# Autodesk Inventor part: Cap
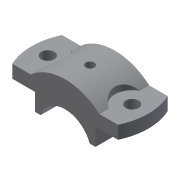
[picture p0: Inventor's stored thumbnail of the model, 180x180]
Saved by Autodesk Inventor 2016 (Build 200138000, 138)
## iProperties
Created: 2009-04
Part Number: Cap
Document SubType Name: Modeling
Designer: Sham
Density: 1 g/cm^3
Material: Generic
Appearance: Default
Author: Sham
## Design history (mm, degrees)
sketch "Sketch1"
  geometry: L1 (-48.857, 23)-(48.857, 23); L2 (48.857, -23)-(-48.857, -23); A1 r 54 centre (0, 0) between (-48.857, 23) and (-48.857, -23); A2 r 54 centre (0, 0) between (48.857, -23) and (48.857, 23); 1 further point
  constraints: 4 end point, 4 point on circle, 2 centre point, 2 coincident, 1 horizontal, 1 parallel, 1 other
  dimensions: "d3" = 54 radius of A1; "d4" = 54 radius of A2; "d5" = 46 distance between parallel lines of L2 L1; "d6" = 23 distance from line of point (0, 0) L1
extrude "Extrusion1" new body sketch "Sketch1" distance "d7" = 12; taper "d8" = 0 deg
sketch "Sketch3"
  geometry: L1 (20.906, 0)-(20.906, -16); L2 (76.906, -0.137)-(76.906, -16.137); L3 (20.906, -16)-(26.23, -16); L4 (71.532, -16.137)-(76.906, -16.137); L5 (76.906, -0.137)-(76.857, 12); L6 (97.714, 0)-(0, 0) reference; L7 (76.857, 12)-(80.606, 12); L8 (17.108, 12)-(20.906, 12); L9 (20.906, 12)-(20.906, 0); L10 (0, 12)-(97.714, 12) reference; A1 r 24 centre (48.857, -24) between (71.532, -16.137) and (26.23, -16); A2 r 48 centre (48.857, -24) between (80.606, 12) and (17.108, 12); 3 further points
  constraints: 16 end point, 4 point on circle, 3 parallel, 3 perpendicular, 2 centre point, 2 coincident, 2 vertical alignment, 1 collinear, 1 midpoint, 1 vertical, 2 other
  dimensions: "d17" = 48 diameter of A1; "d18" = 16 distance of L1.start L1.end; "d19" = 56 distance between parallel lines of L2 L1; "d21" = 8 vertical distance of A1.centre L1.end; "d22" = 48 radius of A2; "d23" = 0 distance from line of L6 L1.start; "d38" = 31.74902 distance of L7.end point (48.857, 12); "d39" = 28 distance from line of point (48.857, 12) L5
extrude "Extrusion2" join sketch "Sketch3" stored distance "d24" = 12; taper "d25" = 0 deg
sketch "Sketch4"
  geometry: 2 further points
  dimensions: "d26" = 78 distance of point (39, 0) point (-39, 0)
hole "Hole1" sketch "Sketch4" at (-39, 0), (39, 0) diameter "d28" = 12; stored, may be unused: countersink angle "d32" = 90 deg, drill point angle "d34" = 118 deg; dims "d29" = 6, "d30" = 4, "d31" = 2, "d33" = 8
sketch "Sketch5"
  geometry: L1 (-31.749, -23)-(-31.749, 23) reference; L2 (-31.749, 14.263)-(-31.749, -14.263); C1 r 6 at (-39, 0) reference; A1 r 16 centre (-39, 0) between (-31.749, -14.263) and (-31.749, 14.263)
  constraints: 2 end point, 2 point on circle, 1 centre point, 1 coincident, 1 collinear, 1 point on line
  dimensions: "d35" = 16 radius of A1
extrude "Extrusion3" cut sketch "Sketch5" distance "d36" = 12; taper "d37" = 0 deg
mirror "Mirror2"
workplane "Work Plane4"
sketch "Sketch6"
  geometry: L1 (-31.749, 0)-(31.749, 0) reference; 1 further point
  dimensions: "d40" = 23 distance from line of L1 point (0, 23)
hole "Hole2" sketch "Sketch6" at (0, 23) diameter "d41" = 6; stored, may be unused: countersink angle "d45" = 90 deg, drill point angle "d47" = 118 deg; dims "d42" = 6, "d43" = 8, "d44" = 16, "d46" = 8
body "Solid1"
